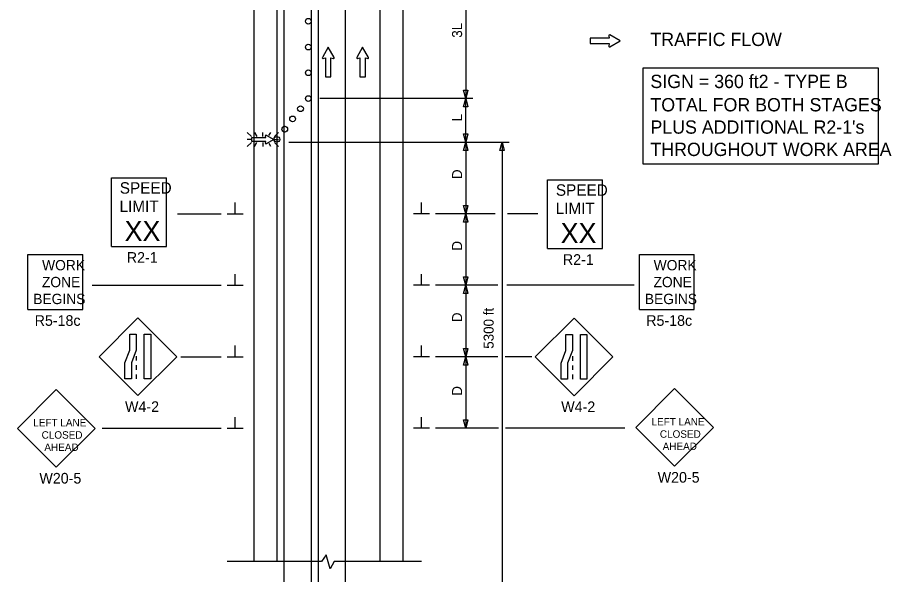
# Model space of a CAD drawing. Extents: x 16794 to 19504, y 7009 to 8243.
# Drawn here: x 16810 to 17421, y 7546 to 7935 of the extents above; entities that cross this region are included whole.
import ezdxf

# ---------------------------------------------------------------- set-up
doc = ezdxf.new("R2010")
doc.units = 0
for name, color, linetype in [('ALI_LEGAL_EX', 7, 'Continuous'), ('MT_SCRATCH_LEVEL_E', 7, 'Continuous'), ('PAVT_EDGE_EX', 7, 'Continuous'), ('TRAFFIC_SIGNS_PR', 7, 'Continuous'), ('TYPICAL_TEXT_DIMEN_EX', 7, 'Continuous'), ('TYPICAL_TEXT_DIMEN_PR', 7, 'Continuous')]:
    doc.layers.add(name, color=color, linetype=linetype)

msp = doc.modelspace()

# ---------------------------------------------------------------- linework, layer by layer
at = {"layer": 'ALI_LEGAL_EX'}
for p, q in [((16995.95, 8243.16), (16995.95, 7425.02)), ((17019.95, 8243.16), (17019.95, 7425.02))]:
    msp.add_line(p, q, dxfattribs=at)
for points in [[(17039.15, 7844.87), (17039.15, 7869.87)], [(17015.15, 7769.87), (17015.15, 7744.87)], [(17039.15, 7744.87), (17039.15, 7769.87)], [(17015.15, 7669.87), (17015.15, 7644.87)], [(17039.15, 7644.87), (17039.15, 7669.87)], [(17015.15, 7569.87), (17015.15, 7554.65)], [(17039.15, 7554.65), (17039.15, 7569.87)]]:
    msp.add_lwpolyline(points, dxfattribs=at)
at = {"layer": 'MT_SCRATCH_LEVEL_E'}
for p, q in [((17223.46, 7920.49), (17210.2, 7920.49)), ((17210.2, 7920.49), (17210.2, 7916.75)), ((17223.14, 7922.27), (17223.46, 7920.49)), ((17231.06, 7918.64), (17223.83, 7922.75)), ((17027.06, 7914.32), (17022.94, 7907.08)), ((17031.2, 7907.08), (17027.06, 7914.32)), ((17051.11, 7914.32), (17047, 7907.08)), ((17055.26, 7907.08), (17051.11, 7914.32)), ((17210.2, 7916.75), (17223.46, 7916.75)), ((17223.46, 7916.75), (17223.14, 7914.97)), ((17223.83, 7914.49), (17231.06, 7918.64)), ((17023.43, 7906.4), (17025.2, 7906.71)), ((17025.2, 7906.71), (17025.2, 7893.45)), ((17028.95, 7893.45), (17028.95, 7906.71)), ((17028.95, 7906.71), (17030.72, 7906.4)), ((17047.48, 7906.4), (17049.26, 7906.71)), ((17049.26, 7906.71), (17049.26, 7893.45)), ((17053, 7893.45), (17053, 7906.71)), ((17053, 7906.71), (17054.78, 7906.4)), ((17025.2, 7893.45), (17028.95, 7893.45)), ((17049.26, 7893.45), (17053, 7893.45))]:
    msp.add_line(p, q, dxfattribs=at)
for centre, start, end in [((17223.6, 7922.34), 60.42484, 189.96381), ((17223.6, 7914.9), 170.03619, 299.77312), ((17023.35, 7906.85), 150.42484, 279.96381), ((17030.79, 7906.86), 260.03619, 29.77312), ((17047.41, 7906.85), 150.42484, 279.96381), ((17054.85, 7906.86), 260.03619, 29.77312)]:
    msp.add_arc(centre, 0.463, start, end, dxfattribs=at)
at = {"layer": 'PAVT_EDGE_EX'}
for p, q in [((16975.15, 8215.07), (16975.15, 7554.65)), ((16991.15, 8215.07), (16991.15, 7554.65)), ((17063.15, 8215.07), (17063.15, 7554.65)), ((17079.15, 8215.07), (17079.15, 7554.65)), ((17015.15, 8169.87), (17015.15, 7340.69)), ((17039.15, 7344.87), (17039.15, 8169.87))]:
    msp.add_line(p, q, dxfattribs=at)
at = {"layer": 'TRAFFIC_SIGNS_PR'}
for p, q in [((16973.31, 7851.74), (16970.49, 7854.56)), ((16977.26, 7851.74), (16975.64, 7854.56)), ((16981.4, 7851.74), (16981.4, 7854.56)), ((16985.58, 7852.38), (16986.84, 7854.56)), ((16992.3, 7854.56), (16989.49, 7851.74)), ((16973.31, 7849.71), (16970.49, 7849.71)), ((16973.31, 7847.68), (16970.49, 7844.86)), ((16975.61, 7844.86), (16977.24, 7847.68)), ((16981.4, 7847.68), (16981.4, 7844.86)), ((16986.87, 7844.86), (16985.66, 7846.95)), ((16989.49, 7849.71), (16992.3, 7849.71)), ((16992.3, 7844.86), (16989.49, 7847.68)), ((16875.57, 7822.99), (16913.97, 7822.99)), ((16875.57, 7774.99), (16875.57, 7822.99)), ((16913.97, 7774.99), (16913.97, 7822.99)), ((17180.43, 7821.51), (17218.83, 7821.51)), ((17180.43, 7773.51), (17180.43, 7821.51)), ((17218.83, 7773.51), (17218.83, 7821.51)), ((16875.57, 7774.99), (16913.97, 7774.99)), ((17180.43, 7773.51), (17218.83, 7773.51)), ((16817.02, 7730.88), (16817.02, 7769.28)), ((16817.02, 7769.28), (16855.42, 7769.28)), ((16855.42, 7730.88), (16855.42, 7769.28)), ((17244.57, 7730.88), (17244.57, 7769.28)), ((17244.57, 7769.28), (17282.97, 7769.28)), ((17282.97, 7730.88), (17282.97, 7769.28)), ((16817.02, 7730.88), (16855.42, 7730.88)), ((17244.57, 7730.88), (17282.97, 7730.88)), ((16894.05, 7724.98), (16866.9, 7697.83)), ((16921.2, 7697.83), (16894.05, 7724.98)), ((17198.97, 7724.88), (17171.82, 7697.73)), ((17226.12, 7697.73), (17198.97, 7724.88)), ((16866.9, 7697.83), (16894.05, 7670.68)), ((16892.8, 7698.32), (16892.8, 7695.12)), ((16894.05, 7670.68), (16921.2, 7697.83)), ((17171.82, 7697.73), (17198.97, 7670.57)), ((17197.72, 7698.22), (17197.72, 7695.02)), ((17198.97, 7670.57), (17226.12, 7697.73)), ((16892.8, 7691.92), (16892.8, 7688.72)), ((17197.72, 7691.82), (17197.72, 7688.62)), ((16892.8, 7685.52), (16892.8, 7682.32)), ((17197.72, 7685.42), (17197.72, 7682.22)), ((16836.97, 7674.92), (16809.81, 7647.77)), ((16864.12, 7647.77), (16836.97, 7674.92)), ((17269.19, 7675.57), (17242.03, 7648.42)), ((17296.34, 7648.42), (17269.19, 7675.57)), ((16809.81, 7647.77), (16836.97, 7620.62)), ((16836.97, 7620.62), (16864.12, 7647.77)), ((17242.03, 7648.42), (17269.19, 7621.26)), ((17269.19, 7621.26), (17296.34, 7648.42))]:
    msp.add_line(p, q, dxfattribs=at)
for points in [[(16983.23, 7847.03), (16983.46, 7848.32), (16973.73, 7848.32), (16973.73, 7851.07), (16983.46, 7851.07), (16983.22, 7852.37)], [(16983.73, 7852.72), (16989.04, 7849.71), (16983.73, 7846.67)]]:
    msp.add_lwpolyline(points, dxfattribs=at)
for points in [[(16892.8, 7713.57), (16892.8, 7702.39), (16889.46, 7693.5), (16889.46, 7682.32), (16884.97, 7682.32), (16884.97, 7693.5), (16888.31, 7702.39), (16888.31, 7713.57)], [(16902.94, 7713.57), (16902.94, 7682.32), (16898.45, 7682.32), (16898.45, 7713.57)], [(17197.72, 7713.46), (17197.72, 7702.28), (17194.38, 7693.4), (17194.38, 7682.22), (17189.88, 7682.22), (17189.88, 7693.4), (17193.23, 7702.28), (17193.23, 7713.46)], [(17207.86, 7713.46), (17207.86, 7682.22), (17203.36, 7682.22), (17203.36, 7713.46)]]:
    msp.add_lwpolyline(points, close=True, dxfattribs=at)
for centre in [(17013.14, 7932.32), (17013.14, 7914.32), (17013.14, 7896.32), (17013.14, 7878.32), (17013.14, 7878.32), (17013.14, 7878.32), (17013.14, 7878.32), (17007.65, 7871.19), (17002.15, 7864.06), (16996.65, 7856.93), (16991.15, 7849.81)]:
    msp.add_circle(centre, 2, dxfattribs=at)
for centre, start, end in [((16983.56, 7852.42), 61.10835, 189.26922), ((16983.56, 7846.97), 170.04067, 298.51671)]:
    msp.add_arc(centre, 0.341, start, end, dxfattribs=at)
at = {"layer": 'TYPICAL_TEXT_DIMEN_EX'}
msp.add_lwpolyline([(17247.21, 7899.69), (17411.46, 7899.69), (17411.46, 7832.52), (17247.21, 7832.52)], close=True, dxfattribs=at)
at = {"layer": 'TYPICAL_TEXT_DIMEN_PR'}
for p, q in [((17123.24, 7970.37), (17123.15, 7878.32)), ((17123.15, 7878.32), (17121.58, 7884.18)), ((17121.58, 7884.18), (17123.15, 7884.18)), ((17123.15, 7884.18), (17124.72, 7884.18)), ((17124.72, 7884.18), (17123.15, 7878.32)), ((17128.15, 7878.32), (17021.23, 7878.32)), ((17121.58, 7872.46), (17123.15, 7878.32)), ((17123.15, 7847.81), (17123.15, 7878.32)), ((17123.15, 7878.32), (17124.72, 7872.46)), ((17123.15, 7872.46), (17121.58, 7872.46)), ((17124.72, 7872.46), (17123.15, 7872.46)), ((17123.15, 7847.81), (17121.58, 7853.67)), ((17121.58, 7853.67), (17123.15, 7853.67)), ((17123.15, 7853.67), (17124.72, 7853.67)), ((17124.72, 7853.67), (17123.15, 7847.81)), ((16999.55, 7847.81), (17153.59, 7847.81)), ((17121.58, 7841.94), (17123.15, 7847.81)), ((17123.15, 7847.81), (17123.15, 7797.81)), ((17123.15, 7847.81), (17124.72, 7841.94)), ((17123.15, 7847.81), (17123.15, 7797.81)), ((17147.02, 7841.94), (17148.59, 7847.81)), ((17148.59, 7847.81), (17150.16, 7841.94)), ((17148.59, 7847.81), (17148.59, 7497.81)), ((17123.15, 7841.94), (17121.58, 7841.94)), ((17124.72, 7841.94), (17123.15, 7841.94)), ((17148.59, 7841.94), (17147.02, 7841.94)), ((17150.16, 7841.94), (17148.59, 7841.94)), ((16962.03, 7797.81), (16962.03, 7805.59)), ((16962.03, 7797.81), (16962.03, 7805.59)), ((17092.28, 7797.81), (17092.28, 7805.59)), ((17123.15, 7797.81), (17121.58, 7803.67)), ((17121.58, 7803.67), (17123.15, 7803.67)), ((17123.15, 7803.67), (17124.72, 7803.67)), ((17124.72, 7803.67), (17123.15, 7797.81)), ((16921.68, 7797.81), (16952.15, 7797.81)), ((16926.15, 7797.81), (16952.15, 7797.81)), ((16956.4, 7797.81), (16967.65, 7797.81)), ((16956.4, 7797.81), (16967.65, 7797.81)), ((17097.9, 7797.81), (17086.65, 7797.81)), ((17143.77, 7797.81), (17102.15, 7797.81)), ((17121.58, 7791.94), (17123.15, 7797.81)), ((17123.15, 7797.81), (17123.15, 7747.81)), ((17123.15, 7797.81), (17124.72, 7791.94)), ((17173.66, 7797.81), (17152.3, 7797.81)), ((17123.15, 7791.94), (17121.58, 7791.94)), ((17124.72, 7791.94), (17123.15, 7791.94)), ((16962.03, 7747.81), (16962.03, 7755.59)), ((16962.03, 7747.81), (16962.03, 7755.59)), ((17092.28, 7747.81), (17092.28, 7755.59)), ((16862.09, 7747.81), (16952.15, 7747.81)), ((16944.38, 7747.81), (16952.15, 7747.81)), ((16956.4, 7747.81), (16967.65, 7747.81)), ((16956.4, 7747.81), (16967.65, 7747.81)), ((17097.9, 7747.81), (17086.65, 7747.81)), ((17145.59, 7747.81), (17102.15, 7747.81)), ((17123.15, 7747.81), (17121.58, 7753.67)), ((17121.58, 7753.67), (17123.15, 7753.67)), ((17121.58, 7741.94), (17123.15, 7747.81)), ((17123.15, 7753.67), (17124.72, 7753.67)), ((17124.72, 7753.67), (17123.15, 7747.81)), ((17123.15, 7747.81), (17123.15, 7697.81)), ((17123.15, 7747.81), (17124.72, 7741.94)), ((17240.98, 7747.81), (17151.82, 7747.81)), ((17123.15, 7741.94), (17121.58, 7741.94)), ((17124.72, 7741.94), (17123.15, 7741.94)), ((16962.03, 7697.81), (16962.03, 7705.59)), ((16962.03, 7697.81), (16962.03, 7705.59)), ((17092.28, 7697.81), (17092.28, 7705.59)), ((17123.15, 7697.81), (17121.58, 7703.67)), ((17121.58, 7703.67), (17123.15, 7703.67)), ((17123.15, 7703.67), (17124.72, 7703.67)), ((17124.72, 7703.67), (17123.15, 7697.81)), ((16924.04, 7697.81), (16952.15, 7697.81)), ((16956.4, 7697.81), (16967.65, 7697.81)), ((16956.4, 7697.81), (16967.65, 7697.81)), ((17097.9, 7697.81), (17086.65, 7697.81)), ((17145.59, 7697.81), (17102.15, 7697.81)), ((17121.58, 7691.94), (17123.15, 7697.81)), ((17123.15, 7697.81), (17123.15, 7647.81)), ((17123.15, 7697.81), (17124.72, 7691.94)), ((17169.48, 7697.81), (17150.69, 7697.81)), ((17123.15, 7691.94), (17121.58, 7691.94)), ((17124.72, 7691.94), (17123.15, 7691.94)), ((16962.03, 7647.81), (16962.03, 7655.59)), ((17092.28, 7647.81), (17092.28, 7655.59)), ((17123.15, 7647.81), (17121.58, 7653.67)), ((17121.58, 7653.67), (17123.15, 7653.67)), ((17123.15, 7653.67), (17124.72, 7653.67)), ((17124.72, 7653.67), (17123.15, 7647.81)), ((16868.92, 7647.81), (16952.15, 7647.81)), ((16956.4, 7647.81), (16967.65, 7647.81)), ((17097.9, 7647.81), (17086.65, 7647.81)), ((17145.99, 7647.81), (17102.15, 7647.81)), ((17234.36, 7647.81), (17151.02, 7647.81)), ((17025.67, 7559.45), (17022.41, 7554.65)), ((17028.41, 7549.51), (17025.67, 7559.45)), ((17022.41, 7554.65), (16956.47, 7554.65)), ((17031.15, 7554.65), (17028.41, 7549.51)), ((17092.32, 7554.65), (17031.15, 7554.65))]:
    msp.add_line(p, q, dxfattribs=at)

# ---------------------------------------------------------------- texts
at = {"layer": 'TRAFFIC_SIGNS_PR'}
for s, height, p in [('SPEED', 8, (16881.34, 7811.85)), ('SPEED', 8, (17186.2, 7810.37)), ('LIMIT', 8, (16881.18, 7799.05)), ('LIMIT', 8, (17186.04, 7797.57)), ('XX', 14.031, (16884.69, 7778.75)), ('XX', 14.031, (17189.54, 7777.27)), ('R2-1', 7.44, (16886.25, 7763.55)), ('R2-1', 7.44, (17191.11, 7762.07)), ('WORK', 7.217, (16827.02, 7758.25)), ('WORK', 7.217, (17254.56, 7758.25)), ('ZONE', 7.217, (16826.9, 7746.44)), ('ZONE', 7.217, (17254.45, 7746.44)), ('BEGINS', 7.217, (16820.83, 7734.63)), ('BEGINS', 7.217, (17248.38, 7734.63)), ('R5-18c', 7.44, (16821.83, 7719.44)), ('R5-18c', 7.44, (17249.38, 7719.44)), ('W4-2', 7.44, (16885.01, 7659.24)), ('W4-2', 7.44, (17189.93, 7659.13)), ('LEFT LANE', 5.2, (16820.85, 7649.17)), ('LEFT LANE', 5.2, (17253.07, 7649.81)), ('CLOSED', 5.2, (16826.68, 7640.57)), ('CLOSED', 5.2, (17258.9, 7641.21)), ('AHEAD', 5.2, (17260.84, 7632.61)), ('AHEAD', 5.2, (16828.62, 7631.97)), ('W20-5', 7.44, (16825.14, 7609.18)), ('W20-5', 7.44, (17257.36, 7609.82))]:
    msp.add_text(s, height=height, dxfattribs=at).set_placement(p)
at = {"layer": 'TYPICAL_TEXT_DIMEN_EX'}
for s, p in [('TRAFFIC FLOW', (17252.28, 7915.05)), ('SIGN = 360 ft2 - TYPE B', (17252.28, 7885.65)), ('TOTAL FOR BOTH STAGES', (17252.28, 7869.35)), ("PLUS ADDITIONAL R2-1's", (17252.28, 7853.75)), ('THROUGHOUT WORK AREA', (17252.28, 7838.15))]:
    msp.add_text(s, height=9.3, dxfattribs=at).set_placement(p)
at = {"layer": 'TYPICAL_TEXT_DIMEN_PR'}
for s, p in [('3L', (17120.64, 7920.85)), ('L', (17120.59, 7862.42)), ('D', (17120.59, 7822.02)), ('D', (17120.59, 7772.02)), ('5300 ft', (17142.68, 7703.41)), ('D', (17120.59, 7722.02)), ('D', (17120.59, 7670.59))]:
    msp.add_text(s, height=7, rotation=90, dxfattribs=at).set_placement(p)

doc.saveas('drawing.dxf')
